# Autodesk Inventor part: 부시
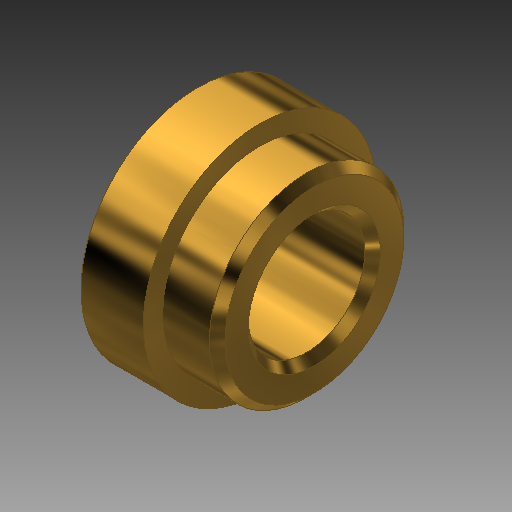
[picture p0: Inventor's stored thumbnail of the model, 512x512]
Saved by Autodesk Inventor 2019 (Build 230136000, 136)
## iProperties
Created: 2016-05
Part Number: 부시
Document SubType Name: Modeling
Designer: mduedu
Density: 7.86 g/cm^3
Material: 강철, 연강
Appearance: 황동 - 새틴
Author: mduedu
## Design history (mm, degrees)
sketch "스케치1"
  geometry: L1 (0, 0)-(15, 0); L2 (0, 7.5)-(15, 7.5); L3 (15, 7.5)-(15, 12.5); L4 (15, 12.5)-(8, 12.5); L5 (8, 12.5)-(8, 15); L6 (8, 15)-(0, 15); L7 (0, 15)-(0, 7.5)
  constraints: 14 end point, 4 parallel, 2 vertical alignment, 1 horizontal, 1 perpendicular, 1 vertical
  dimensions: "d0" = 15 distance of L1.start L1.end; "d1" = 15 diameter of L2 L1; "d2" = 25 diameter of L4 L1; "d3" = 8 distance of L5.end L6.end; "d4" = 30 diameter of L6 L1
revolve "회전1" sketch "스케치1" stored, may be unused: angle "d5" = 90 deg
chamfer "모따기1" distance "d6" = 1; stored, may be unused: second distance "d7" = 2, angle "d8" = 45 deg
chamfer "모따기2" distance "d9" = 1; stored, may be unused: second distance "d10" = 2, angle "d11" = 45 deg
node "솔리드1"
